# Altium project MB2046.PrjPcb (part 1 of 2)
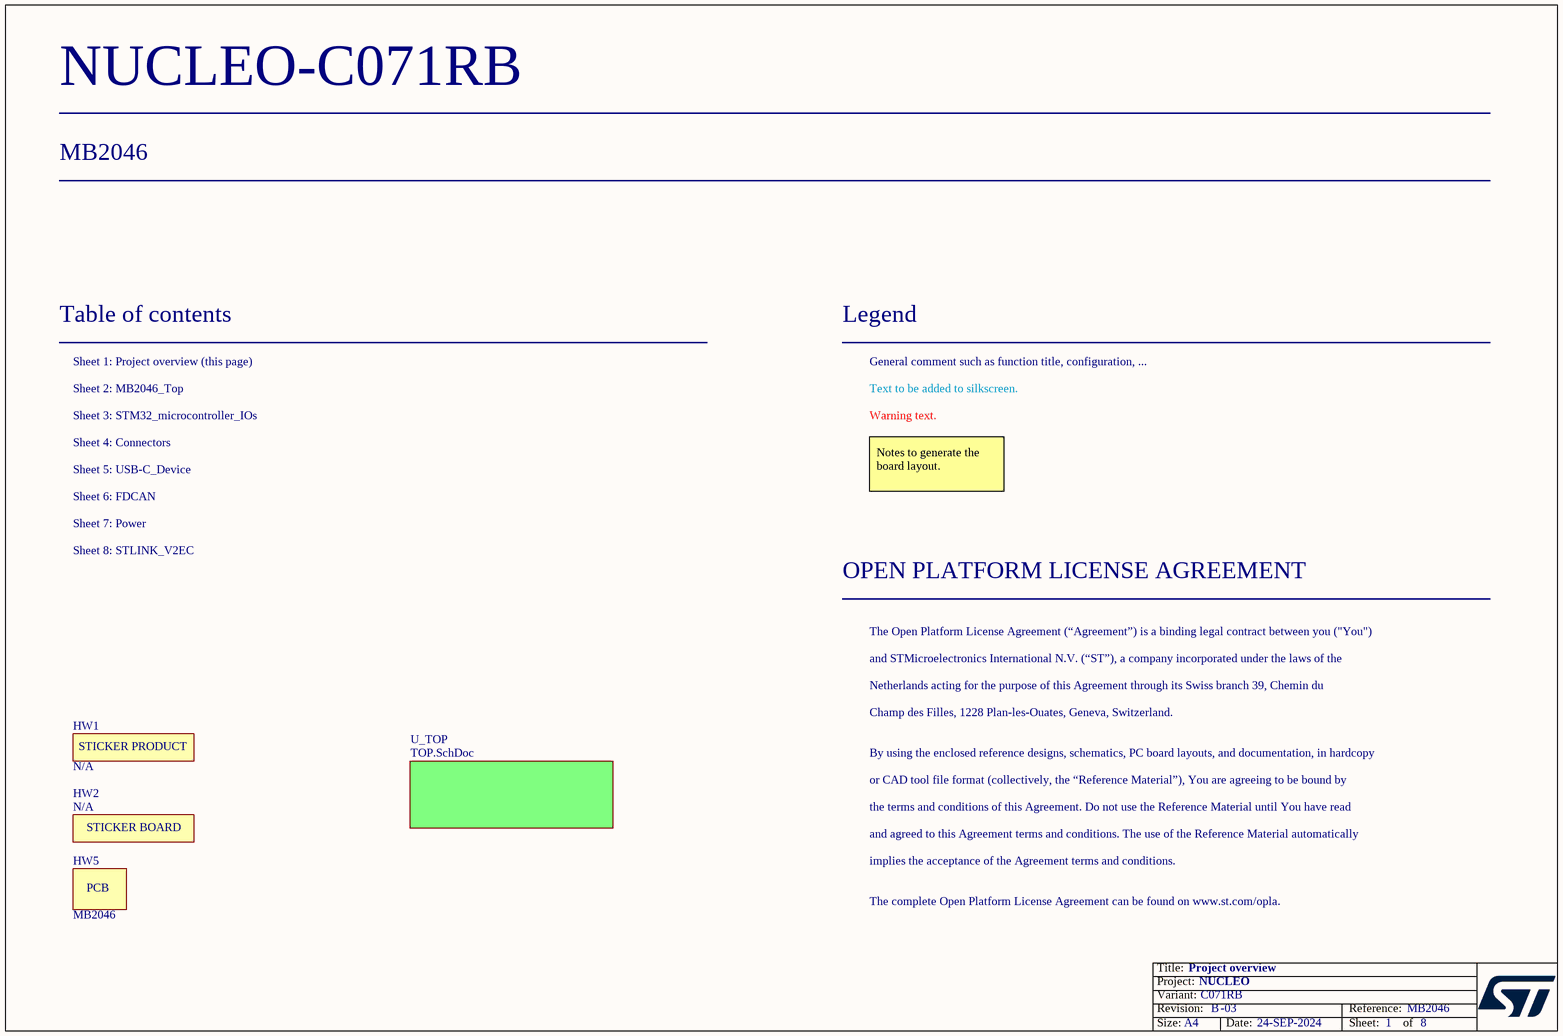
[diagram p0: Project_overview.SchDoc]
VariantName: C071RB; Board_Reference: MB2046; Board_PCB_Revision: B; Board_Name: NUCLEO; Board_Document_Date: 24-SEP-2024; Board_Assembly_Revision: 03
8 sheets, 190 parts. Net scope: flat (ports and power ports of the same name join across sheets).
Board file: MB2046.PcbDoc
Sheets:
  Project_overview.SchDoc
    U_TOP = TOP.SchDoc
      Power = Power.SchDoc
      U_STM32_microcontroller_IOs = STM32_microcontroller_IOs.SchDoc
      U_STLINK_V2EC = STLINK_V2EC.SchDoc
      U_USB-C_Device = USB-C_Device.SchDoc
      U_FDCAN = FDCAN.SchDoc
      U_Connectors = Connectors.SchDoc

## Sheet Project_overview.SchDoc: Project overview
size A4; Date: Not used; ApprovedBy: Not used; CheckedBy: Not used; Author: Not used; CompanyName: STMicroelectronics; DrawnBy: Not used; Engineer: Not used; Organization: Not used; Address1: Not used; Address2: Not used; Address3: Not used; Address4: Not used; DocumentNumber: 1; Revision: Not used; SheetNumber: 1; SheetTotal: 8

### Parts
HW1  STICKER_PRODUCT  [STICKER_PRODUCT_25X9]  (value not drawn)  (no BOM)
HW2  STICKER_BOARD  [STICKER_BOARD_25X9]  (value not drawn)  (no BOM)
HW5  value MB2046  (hidden comment: PCB)  (no BOM)

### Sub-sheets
U_TOP = TOP.SchDoc: no entries

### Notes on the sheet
- Table of contents
- Sheet 1: Project overview (this page)
- Legend
- General comment such as function title, configuration, ...
- Sheet 2: MB2046_Top
- Sheet 4: Connectors
- Sheet 3: STM32_microcontroller_IOs
- Text to be added to silkscreen.
- Warning text.
- Sheet 5: USB-C_Device
- Sheet 6: FDCAN
- Notes to generate the board layout.
- Sheet 7: Power
- Sheet 8: STLINK_V2EC
- OPEN PLATFORM LICENSE AGREEMENT
- The Open Platform License Agreement (“Agreement”) is a binding legal contract between you ("You")
- and STMicroelectronics International N.V. (“ST”), a company incorporated under the laws of the
- Netherlands acting for the purpose of this Agreement through its Swiss branch 39, Chemin du
- Champ des Filles, 1228 Plan-les-Ouates, Geneva, Switzerland.
- By using the enclosed reference designs, schematics, PC board layouts, and documentation, in hardcopy
- or CAD tool file format (collectively, the “Reference Material”), You are agreeing to be bound by
- the terms and conditions of this Agreement. Do not use the Reference Material until You have read
- and agreed to this Agreement terms and conditions. The use of the Reference Material automatically
- implies the acceptance of the Agreement terms and conditions.
- The complete Open Platform License Agreement can be found on www.st.com/opla.

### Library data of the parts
HW1 = MCD-00547: Sticker product, 25x9mm; Part_Type: Misc; Part_Preference: Recommended; ShowFields: YES; ID: 3197; Component_Country_Of_Origin: Unknown
HW2 = MCD-00235: Sticker Board, 25x9mm; Part_Type: Misc; Part_Preference: Recommended; ShowFields: YES; ID: 2632; Component_Country_Of_Origin: Unknown
HW5 = MCD-03651: MB2046 PCB; Part_Preference: Recommended; ShowFields: YES; ID: 5767

## Sheet TOP.SchDoc: TOP
size A4; CompanyName: STMicroelectronics; Organization: Microcontrollers Division; SheetNumber: 2; SheetTotal: 8
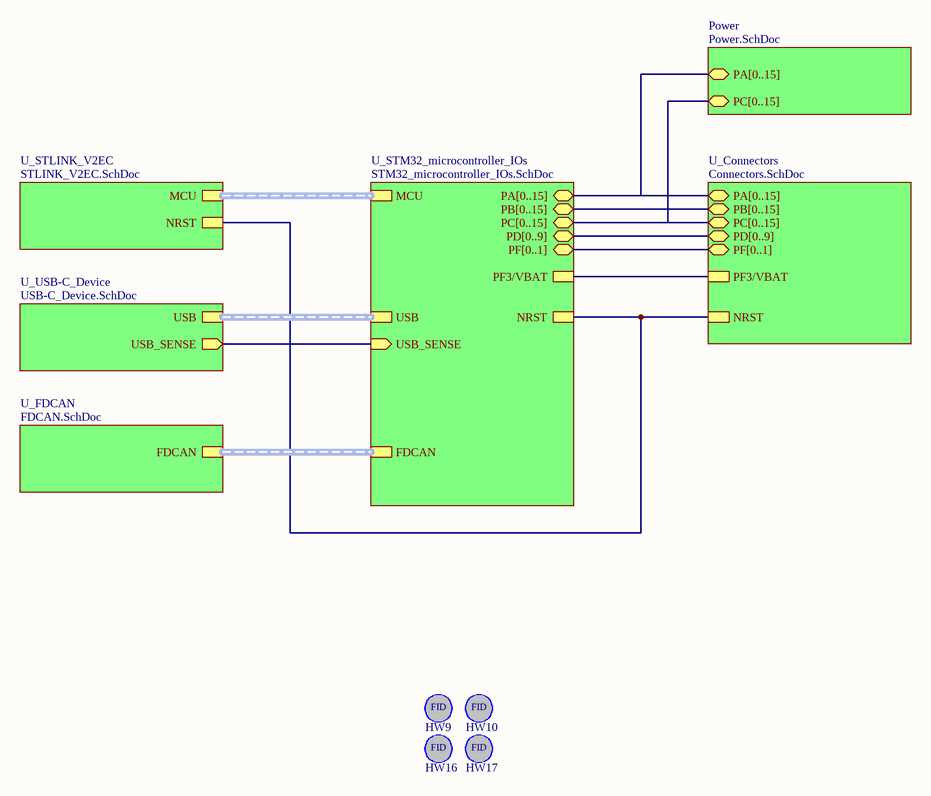
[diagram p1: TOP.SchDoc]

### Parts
HW9  FiducialPad  [MIRE_PLACE_SMD_0P8MM]  (value not drawn)  (no BOM)
HW10  FiducialPad  [MIRE_PLACE_SMD_0P8MM]  (value not drawn)  (no BOM)
HW16  FiducialPad  [MIRE_PLACE_SMD_0P8MM]  (value not drawn)  (no BOM)
HW17  FiducialPad  [MIRE_PLACE_SMD_0P8MM]  (value not drawn)  (no BOM)

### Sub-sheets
Power = Power.SchDoc: PA[0..15] (bidir), PC[0..15] (bidir)
U_Connectors = Connectors.SchDoc: PB[0..15] (bidir), PC[0..15] (bidir), PA[0..15] (bidir), NRST, PD[0..9] (bidir), PF[0..1] (bidir), PF3/VBAT
U_FDCAN = FDCAN.SchDoc: FDCAN (harness FDCAN)
U_STLINK_V2EC = STLINK_V2EC.SchDoc: MCU (harness MCU), NRST
U_STM32_microcontroller_IOs = STM32_microcontroller_IOs.SchDoc: PA[0..15] (bidir), PB[0..15] (bidir), PC[0..15] (bidir), MCU (harness MCU), NRST, USB_SENSE (in), USB (harness USB), PD[0..9] (bidir), PF[0..1] (bidir), PF3/VBAT, FDCAN (harness FDCAN)
U_USB-C_Device = USB-C_Device.SchDoc: USB (harness USB), USB_SENSE (out)

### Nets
(unnamed): sheet U_STM32_microcontroller_IOs/NRST, sheet U_STLINK_V2EC/NRST, sheet U_Connectors/NRST
(unnamed): sheet U_STM32_microcontroller_IOs/USB_SENSE, sheet U_USB-C_Device/USB_SENSE  [a separate net that carries the same name]
(unnamed): sheet U_STM32_microcontroller_IOs/PF3/VBAT, sheet U_Connectors/PF3/VBAT  [a separate net that carries the same name]

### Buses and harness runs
bus sheet Power/PA[0..15] = sheet U_Connectors/PA[0..15] = sheet U_STM32_microcontroller_IOs/PA[0..15]
bus sheet Power/PC[0..15] = sheet U_Connectors/PC[0..15] = sheet U_STM32_microcontroller_IOs/PC[0..15]
bus sheet U_Connectors/PB[0..15] = sheet U_STM32_microcontroller_IOs/PB[0..15]
bus sheet U_Connectors/PD[0..9] = sheet U_STM32_microcontroller_IOs/PD[0..9]
bus sheet U_Connectors/PF[0..1] = sheet U_STM32_microcontroller_IOs/PF[0..1]
harness sheet U_FDCAN/FDCAN = sheet U_STM32_microcontroller_IOs/FDCAN
harness sheet U_STLINK_V2EC/MCU = sheet U_STM32_microcontroller_IOs/MCU
harness sheet U_STM32_microcontroller_IOs/USB = sheet U_USB-C_Device/USB

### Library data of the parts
HW9 HW10 HW16 HW17 = MCD-03135: Fiducial Pad, 0.8mm; Part_Type: Misc; Part_Preference: Recommended; ShowFields: YES; ID: 5251; Component_Country_Of_Origin: Unknown

## Sheet Power.SchDoc: Power
size A4; CompanyName: STMicroelectronics; Organization: Microcontrollers Division; SheetNumber: 7; SheetTotal: 8
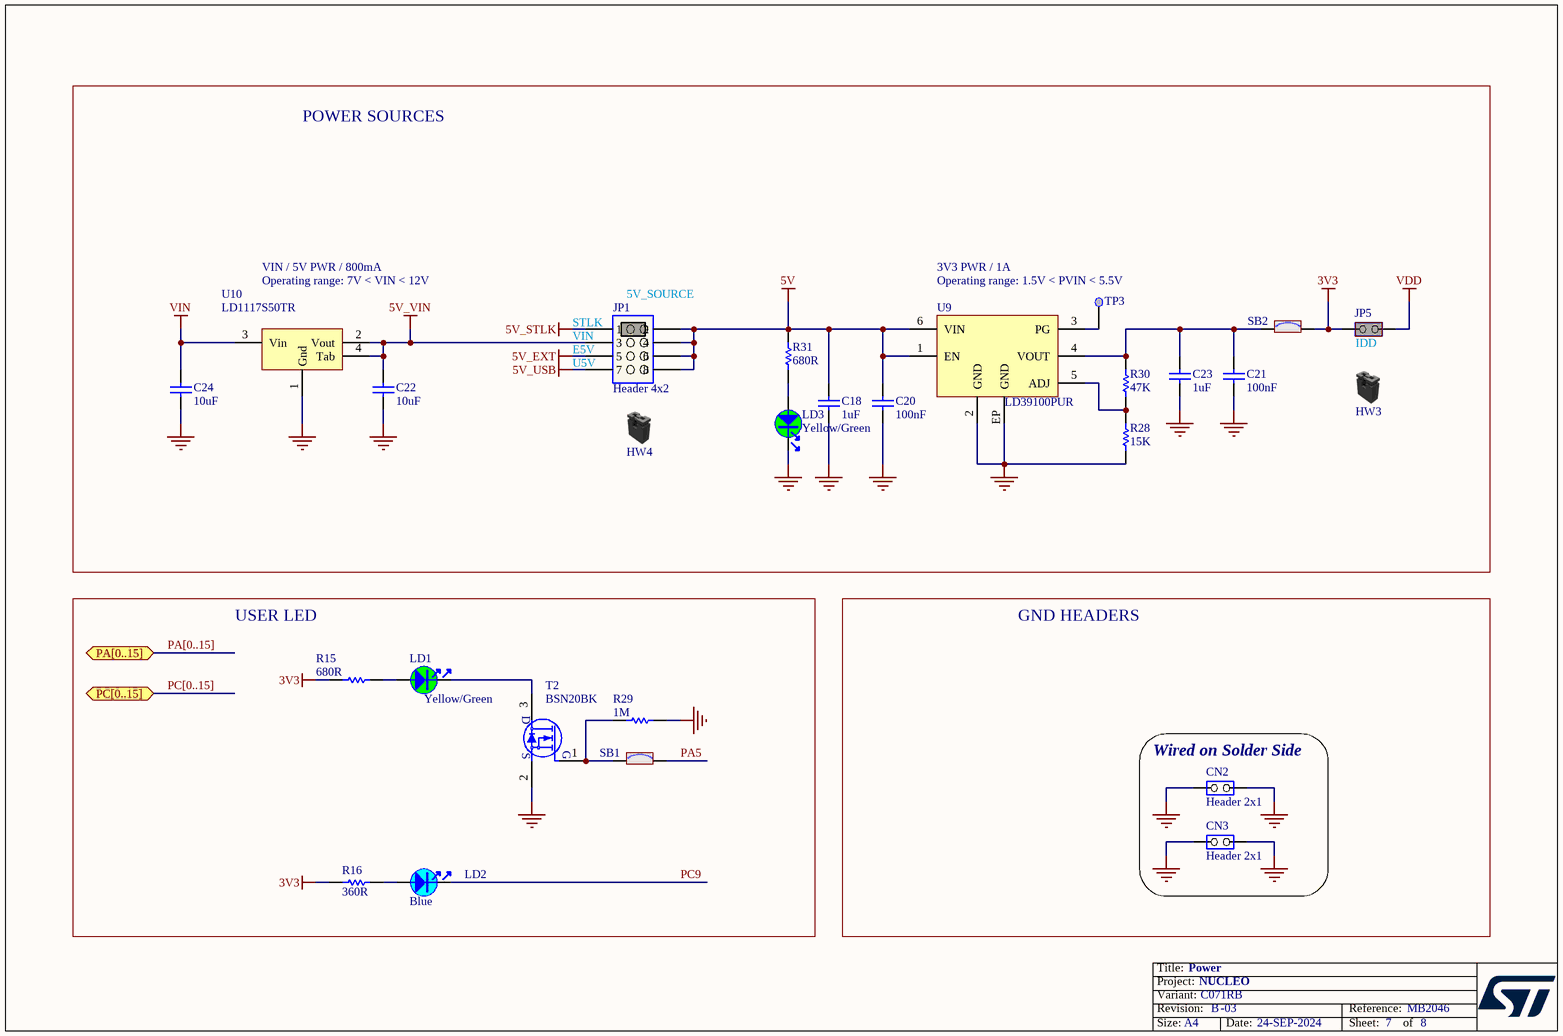
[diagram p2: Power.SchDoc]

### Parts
C18  value 1uF  [C0603]  (hidden comment: Capacitor)
C20  value 100nF  [C0402]  (hidden comment: Capacitor)
C21  value 100nF  [C0402]  (hidden comment: Capacitor)
C22  value 10uF  [C0805]  (hidden comment: Capacitor)
C23  value 1uF  [C0603]  (hidden comment: Capacitor)
C24  value 10uF  [C0805]  (hidden comment: Capacitor)
CN2  value Header 2x1  [CON_SAMTEC_TSW-102-09-X-S]  (hidden comment: Jumper_Header 2x1)
CN3  value Header 2x1  [CON_SAMTEC_TSW-102-09-X-S]  (hidden comment: Jumper_Header 2x1)
HW3  Shunt Black 2.54mm  (value not drawn)  (mechanical)
HW4  Shunt Black 2.54mm  (value not drawn)  (mechanical)
JP1  value Header 4x2  [CON_SAMTEC_TSW-104-07-X-D]  (hidden comment: Jumper_Header 4x2 Fitted 1-2)
JP5  Jumper_Header 2x1 Fitted  [CON_SAMTEC_TSW-102-07-G-S]  (value not drawn)
LD1  value Yellow/Green  [LED_0402_EVERLIGHT_16-213SYGC/S530-E3-TR8 _YELLOW-GREEN_1A2K_H0P45]  (hidden comment: LED_green)
LD2  value Blue  [LED_0402_KINGBRIGHT_KPHHS-1005QBC-D-V_BLUE_1A2K_H0P5]  (hidden comment: LED_blue)
LD3  value Yellow/Green  [LED_0402_EVERLIGHT_16-213SYGC/S530-E3-TR8 _YELLOW-GREEN_1A2K_H0P45]  (hidden comment: LED_green)
R15  value 680R  [R0402]  (hidden comment: Resistor)
R16  value 360R  [R0402]  (hidden comment: Resistor)
R28  value 15K  [R0402]  (hidden comment: Resistor)
R29  value 1M  [R0402]  (hidden comment: Resistor)
R30  value 47K  [R0402]  (hidden comment: Resistor)
R31  value 680R  [R0402]  (hidden comment: Resistor)
SB1  SB_ON  [SOLDER-BRIDGE_R0603-0R]  (value not drawn)
SB2  SB_ON  [SOLDER-BRIDGE_R0603-0R]  (value not drawn)
T2  value BSN20BK  [MOS_SOT23]  (hidden comment: BSN20)
TP3  Test Point  [TP_SMD_1MM]  (value not drawn)  (no BOM)
U9  LD39100PUR  [ICC_DFN6-EPAD_3X3_P095]
U10  LD1117S50TR  [REG_SOT223-TAB]

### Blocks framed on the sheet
POWER SOURCES: C18 C20-C24 HW3 HW4 JP1 JP5 LD3 R28 R30 R31 SB2 TP3 U9 U10
USER LED: LD1 LD2 R15 R16 R29 SB1 T2
Wired on Solder Side: CN2 CN3

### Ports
PA[0..15] (bidir), PC[0..15] (bidir)

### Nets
3V3: JP5.2(NO) R15.2 R16.2 SB2.2
5V: C18.2 C20.2 JP1.2 JP1.4 JP1.6 JP1.8 R31.1 U9.1(EN) U9.6(VIN)
5V_EXT: JP1.5
5V_STLK: JP1.1
5V_USB: JP1.7
5V_VIN: C22.2 JP1.3 U10.2(Vout) U10.4(Tab)
GND: C18.1 C20.1 C21.1 C22.1 C23.1 C24.1 CN2.1(COMMON) CN2.2(NO) CN3.1(COMMON) CN3.2(NO) LD3.2 R28.1 R29.2 T2.2(S) U9.2(GND) U9.EP(GND) U10.1(Gnd)
VDD: JP5.1(COMMON)
VIN: C24.2 U10.3(Vin)
PA5: SB1.2
PC9: LD2.2
NetC21_2: C21.2 C23.2 R30.2 SB2.1 U9.4(VOUT)
NetLD1_1: LD1.1 R15.1
NetLD1_2: LD1.2 T2.3(D)
NetLD2_1: LD2.1 R16.1
NetLD3_1: LD3.1 R31.2
NetR28_2: R28.2 R30.1 U9.5(ADJ)
NetR29_1: R29.1 SB1.1 T2.1(G)
NetTP3_1: TP3.1 U9.3(PG)

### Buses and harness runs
bus PA[0..15] = port PA[0..15]
bus PC[0..15] = port PC[0..15]

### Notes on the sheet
- VIN / 5V PWR / 800mA
- Operating range: 7V < VIN < 12V
- (near JP1) 5V_SOURCE
- 3V3 PWR / 1A
- (near TP3) Operating range: 1.5V < PVIN < 5.5V
- (near JP1) E5V
- (near JP1) VIN
- (near JP1) STLK
- (near JP1) U5V
- (near JP5) IDD
- GND HEADERS

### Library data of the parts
C18 C23 = MCD-00010: Capacitor, MLCC, 1uF, 16V, X5R, +/-10%, 0603, T=0.8mm; Manufacturer_Part_Number: CC0603KRX5R7BB105; Manufacturer: YAGEO; Part_Preference: Recommended; Order_Code_RS: 2370680; Component_Country_Of_Origin: China; ShowFields: YES; ID: 2470
C20 C21 = MCD-00006: Capacitor, MLCC, 100nF, 16V, X7R, +/-10%, 0402, T=0.5mm; Manufacturer_Part_Number: CC0402KRX7R7BB104; Manufacturer: YAGEO; Part_Preference: Recommended; Partial_Alternate_Internal_Part_Number: MCD-03299; Order_Code_RS: 9402047; Component_Country_Of_Origin: China; ShowFields: YES; ID: 2474
C22 C24 = MCD-00014: Capacitor, MLCC, 10uF, 25V, X5R, +/-10%, 0805, T=0.85mm; Manufacturer_Part_Number: CC0805KRX5R8BB106; Manufacturer: YAGEO; Part_Preference: Recommended; Full_Alternate_Internal_Part_Number: MCD-02385; Partial_Alternate_Internal_Part_Number: MCD-03053; Component_Country_Of_Origin: China; ShowFields: YES; ID: 2468
CN2 CN3 = MCD-00214: Header, 2x1, 2.54mm, VR, TH, T=5.84mm/10.16mm; Part_Type: Connector; Manufacturer_Part_Number: TSW-102-09-G-S; Manufacturer: SAMTEC; Part_Preference: Recommended; Full_Alternate_Internal_Part_Number: MCD-02393; Partial_Alternate_Internal_Part_Number: MCD-03591, MCD-03719, MCD-04227; Order_Code_RS: 180-3129; Component_Country_Of_Origin: China, Costa Rica, Malaysia, USA, Vietnam; ShowFields: YES; ID: 2652
HW3 HW4 = MCD-00043: Jumper, 2.54mm, Black, 4.3A, 6.1mm, 5mR; Manufacturer_Part_Number: SNT-100-BK-G; Manufacturer: SAMTEC; Part_Type: Misc; Part_Preference: Recommended; Full_Alternate_Internal_Part_Number: MCD-02388; Partial_Alternate_Internal_Part_Number: MCD-01849, MCD-01864; Manufacturer_HQ_COO: Unknown; Value: SNT-100-BK-G; Component_Country_Of_Origin: China, Costa Rica, Malaysia, USA, Vietnam; ShowFields: YES; ID: 2551; Order_Code_RS: 158-7784; Alternate_EMS: A
JP1 = MCD-00686: Header, 4x2, 2.54mm, VR, TH, T=5.84mm/2.54mm; Part_Type: Connector; Manufacturer_Part_Number: TSW-104-07-G-D; Manufacturer: SAMTEC; Part_Preference: Recommended; Partial_Alternate_Internal_Part_Number: MCD-01661, MCD-03721; Order_Code_RS: 161-2260; Component_Country_Of_Origin: China, Costa Rica, Malaysia, USA, Vietnam; ShowFields: YES; ID: 3062
JP5 = MCD-00683: Header, 2x1, 2.54mm, VR, TH, T=5.84mm/2.54mm; Part_Type: Connector; Manufacturer_Part_Number: TSW-102-07-G-S; Manufacturer: SAMTEC; Part_Preference: Recommended; Full_Alternate_Internal_Part_Number: MCD-02389; Partial_Alternate_Internal_Part_Number: MCD-02957, MCD-03720; Order_Code_RS: 155-5312; Component_Country_Of_Origin: China, Costa Rica, Malaysia, USA, Vietnam; ShowFields: YES; ID: 3057
LD1 LD3 = MCD-02330: LED Bicolor, Yellow/Green, 2V, 25mA, 0402; Part_Type: Display; Manufacturer_Part_Number: 16-213SYGC/S530-E3/TR8; Manufacturer: EVERLIGHT; Part_Preference: Recommended; Component_Country_Of_Origin: China; ShowFields: YES; ID: 4436
LD2 = MCD-00706: LED, Blue, 3V3, 20mA, 0402; Part_Type: Display; Part_Preference: Recommended; Manufacturer: KINGBRIGHT; Manufacturer_Part_Number: KPHHS-1005QBC-D-V; Order_Code_RS: 146-1490; Component_Country_Of_Origin: Unknown; ShowFields: YES; ID: 3040
R15 R31 = MCD-00507: Resistor, 680R, 0402, +/-1%, 1/16W; Manufacturer_Part_Number: RC0402FR-07680RL; Manufacturer: YAGEO; Part_Preference: Recommended; Component_Country_Of_Origin: China; ShowFields: YES; ID: 3238
R16 = MCD-00461: Resistor, 360R, 0402, +/-1%, 1/16W; Manufacturer_Part_Number: RC0402FR-07360RL; Manufacturer: YAGEO; Part_Preference: Recommended; Component_Country_Of_Origin: China; ShowFields: YES; ID: 2816
R28 = MCD-01943: Resistor, 15K, 0402, +/-1%, 1/16W; Part_Preference: Recommended; Manufacturer: YAGEO; Manufacturer_Part_Number: RC0402FR-0715KL; Order_Code_RS: 618-6009; Component_Country_Of_Origin: China; ShowFields: YES; ID: 4043
R29 = MCD-00182: Resistor, 1M, 0402, +/-1%, 1/16W; Manufacturer_Part_Number: RC0402FR-071ML; Manufacturer: YAGEO; Part_Preference: Recommended; BMS_Part_Number: 9131778; Order_Code_RS: 618-6194; Component_Country_Of_Origin: China; ShowFields: YES; ID: 2686
R30 = MCD-00063: Resistor, 47K, 0402, +/-1%, 1/16W; Part_Preference: Recommended; Manufacturer: YAGEO; Manufacturer_Part_Number: RC0402FR-0747KL; Order_Code_RS: 9239430; Component_Country_Of_Origin: China; ShowFields: YES; ID: 2528
SB1 SB2 = MCD-00071: Resistor, 0R, SB0603, 5%, 0.1W; Manufacturer_Part_Number: RC0603JR-070RL; Manufacturer: YAGEO; Part_Preference: Recommended; Manufacturer_HQ_COO: Unknown; ShowFields: YES; ID: 2521; Order_Code_RS: 199-5647; Component_Country_Of_Origin: China
T2 = MCD-01969: Transistor, MOSFET, N-CH, 60V, 265mA, SOT23-3; Manufacturer: NEXPERIA; Part_Preference: Recommended; Order_Code_RS: 136-4845; Component_Country_Of_Origin: China; ShowFields: YES; ID: 4069
TP3 = MCD-00074: Test Point, SMD, 1mm; Part_Type: Misc; Part_Preference: Recommended; ShowFields: YES; ID: 2518; Component_Country_Of_Origin: Unknown
U9 = MCD-03339: LDO, 1V5 to 5V5V, 1A adjustable; Part_Type: IC; Part_Preference: Recommended; Manufacturer: STMICROELECTRONICS; ShowFields: YES; ID: 5455; Component_Country_Of_Origin: Malaysia
U10 = MCD-00088: LDO, Adjustable and fixed low drop positive voltage regulator; Part_Type: IC; Manufacturer: STMICROELECTRONICS; BMS_Part_Number: 9176133; Part_Preference: Recommended; Manufacturer_HQ_COO: EU; Component_Country_Of_Origin: China; ShowFields: YES; ID: 2503; Order_Code_RS: 165-7748

## Sheet STM32_microcontroller_IOs.SchDoc: STM32_microcontroller_IOs
size A4; CompanyName: STMicroelectronics; Organization: Microcontrollers Division; SheetNumber: 3; SheetTotal: 8
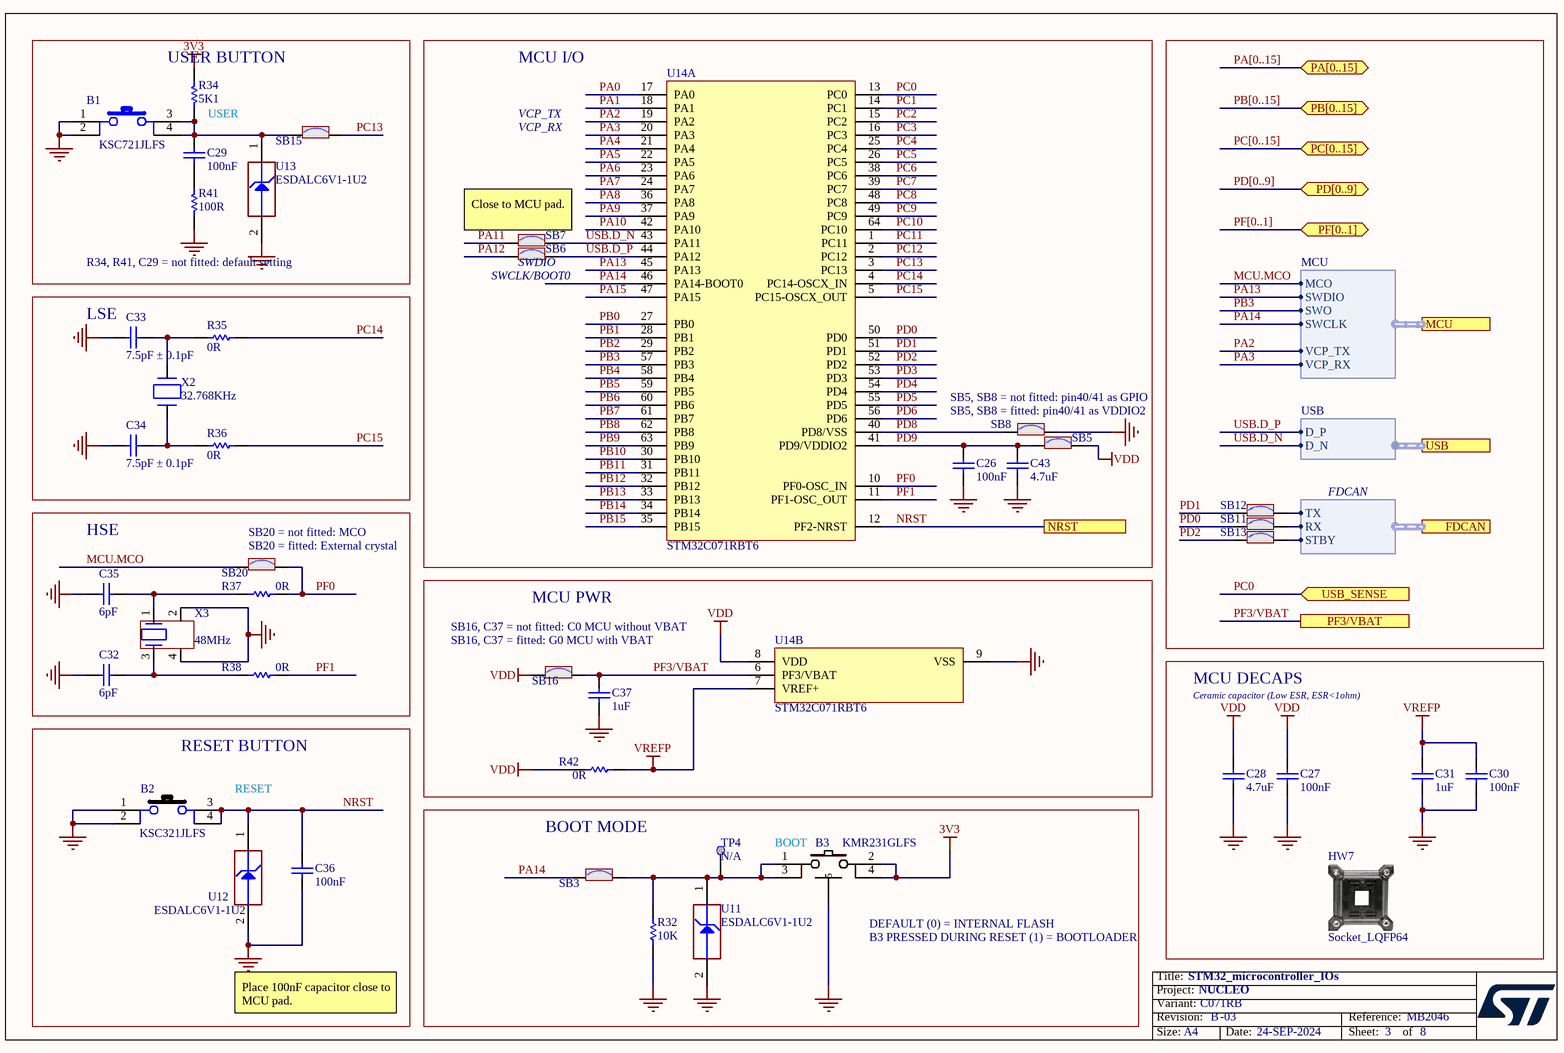
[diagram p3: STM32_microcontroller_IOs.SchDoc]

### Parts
B1  value KSC721JLFS  [SWI_C&K_KSC721JLFS_BLUE]  (hidden comment: SW_BLUE_KSC721JLFS)
B2  value KSC321JLFS  [SWI_C&K_KSC321JLFS_BLACK]  (hidden comment: SW_BLACK_KSC321JLFS)
B3  value KMR231GLFS  [SWI_C&K_Y78B23110FP__ITT_KMR231GLFS]  (hidden comment: SW-PUSH-CMS_KMR2_BLACK)
C26  value 100nF  [C0402]  (hidden comment: Capacitor)
C27  value 100nF  [C0402]  (hidden comment: Capacitor)
C28  value 4.7uF  [C0603_H0P8]  (hidden comment: Capacitor)
C29  value 100nF  [C0402]  (hidden comment: Capacitor)
C30  value 100nF  [C0402]  (hidden comment: Capacitor)
C31  value 1uF  [C0603]  (hidden comment: Capacitor)
C32  value 6pF  [C0402]  (hidden comment: Capacitor)
C33  value 7.5pF ± 0.1pF  [C0402]  (hidden comment: Capacitor)
C34  value 7.5pF ± 0.1pF  [C0402]  (hidden comment: Capacitor)
C35  value 6pF  [C0402]  (hidden comment: Capacitor)
C36  value 100nF  [C0402]  (hidden comment: Capacitor)
C37  value 1uF  [C0603]  (hidden comment: Capacitor)
C43  value 4.7uF  [C0603_H0P8]  (hidden comment: Capacitor)
HW7  SOCKET_LQFP64  (mechanical)
R32  value 10K  [R0402]  (hidden comment: Resistor)
R34  value 5K1  [R0402]  (hidden comment: Resistor)
R35  value 0R  [R0402]  (hidden comment: Resistor)
R36  value 0R  [R0402]  (hidden comment: Resistor)
R37  value 0R  [R0402]  (hidden comment: Resistor)
R38  value 0R  [R0402]  (hidden comment: Resistor)
R41  value 100R  [R0402]  (hidden comment: Resistor)
R42  value 0R  [R0603]  (hidden comment: Resistor)
SB3  SB_ON  [SOLDER-BRIDGE_R0603-0R]  (value not drawn)
SB5  SB_ON  [SOLDER-BRIDGE_R0603-0R]  (value not drawn)
SB6  SB_ON  [SOLDER-BRIDGE_R0603-0R]  (value not drawn)
SB7  SB_ON  [SOLDER-BRIDGE_R0603-0R]  (value not drawn)
SB8  SB_ON  [SOLDER-BRIDGE_R0603-0R]  (value not drawn)
SB11  SB_ON  [SOLDER-BRIDGE_R0603-0R]  (value not drawn)
SB12  SB_ON  [SOLDER-BRIDGE_R0603-0R]  (value not drawn)
SB13  SB_ON  [SOLDER-BRIDGE_R0603-0R]  (value not drawn)
SB15  SB_ON  [SOLDER-BRIDGE_R0603-0R]  (value not drawn)
SB16  SB_ON  [SOLDER-BRIDGE_R0603-0R]  (value not drawn)
SB20  SB_ON  [SOLDER-BRIDGE_R0603-0R]  (value not drawn)
TP4  Test Point  [TP_SMD_0-6MM]  (value not drawn)  (no BOM)
U11  value ESDALC6V1-1U2  [ESD_ST0201]  (hidden comment: ESD-TRANSIL)
U12  value ESDALC6V1-1U2  [ESD_ST0201]  (hidden comment: ESD-TRANSIL)
U13  value ESDALC6V1-1U2  [ESD_ST0201]  (hidden comment: ESD-TRANSIL)
U14  value STM32C071RBT6  [ICC_LQFP64_10X10_P050_SOCKET_YAMAICHI_IC149-064-069-B5_NM]  (hidden comment: STM32C071RB)  (parts A,B of 2)
X2  value 32.768KHz  [CRY_NX2012SA_2P]  (hidden comment: XTAL_2_PINS)
X3  value 48MHz  [CRY_NX1612SA_4P]  (hidden comment: XTAL_4_PINS)

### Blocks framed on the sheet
USER BUTTON: B1 C29 R34 R41 SB15 U13
MCU I/O: C26 C43 SB5-SB8 U14
LSE: C33 C34 R35 R36 X2
HSE: C32 C35 R37 R38 SB20 X3
MCU PWR: C37 R42 SB16 U14
MCU DECAPS: C27 C28 C30 C31 HW7
RESET BUTTON: B2 C36 U12
BOOT MODE: B3 R32 SB3 TP4 U11

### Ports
FDCAN (harness FDCAN), MCU (harness MCU), NRST, PA[0..15] (bidir), PB[0..15] (bidir), PC[0..15] (bidir), PD[0..9] (bidir), PF3/VBAT, PF[0..1] (bidir), USB (harness USB), USB_SENSE (in)

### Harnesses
MCU: MCO, SWDIO, SWO, VCP_TX, SWCLK, VCP_RX
USB: D_P, D_N
FDCAN: TX, RX, STBY

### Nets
3V3: B3.2 B3.4 R34.2
GND: B1.1 B1.2 B2.1 B2.2 B3.5 C26.1 C27.1 C28.1 C30.1 C31.2 C32.1 C33.1 C34.1 C35.1 C36.1 C37.2 C43.1 R32.1 R41.2 SB8.2 U11.2(GND) U12.2(GND) U13.2(GND) U14.9(VSS) X3.2 X3.4
VDD: C27.2 C28.2 R42.1 SB5.2 SB16.1 U14.8(VDD)
VREFP: C30.2 C31.1 R42.2 U14.7(VREF+)
FDCAN_RX: SB11.2 ; port FDCAN.RX
FDCAN_STBY: SB13.2 ; port FDCAN.STBY
FDCAN_TX: SB12.2 ; port FDCAN.TX
MCU.MCO: SB20.1 ; port MCU.MCO
NRST: B2.3 B2.4 C36.2 U12.1(IO1) U14.12(PF2-NRST) ; port NRST
PA0: U14.17(PA0)
PA1: U14.18(PA1)
PA2: U14.19(PA2) ; port MCU.VCP_TX  [project net MCU.VCP_TX]
PA3: U14.20(PA3) ; port MCU.VCP_RX  [project net MCU.VCP_RX]
PA4: U14.21(PA4)
PA5: U14.22(PA5)
PA6: U14.23(PA6)
PA7: U14.24(PA7)
PA8: U14.36(PA8)
PA9: U14.37(PA9)
PA10: U14.42(PA10)
PA11: SB7.1
PA12: SB6.1
PA13: U14.45(PA13) ; port MCU.SWDIO  [project net MCU.SWDIO]
PA14: SB3.1 U14.46(PA14-BOOT0) ; port MCU.SWCLK  [project net MCU.SWCLK]
PA15: U14.47(PA15)
PB0: U14.27(PB0)
PB1: U14.28(PB1)
PB2: U14.29(PB2)
PB3: U14.57(PB3) ; port MCU.SWO  [project net MCU.SWO]
PB4: U14.58(PB4)
PB5: U14.59(PB5)
PB6: U14.60(PB6)
PB7: U14.61(PB7)
PB8: U14.62(PB8)
PB9: U14.63(PB9)
PB10: U14.30(PB10)
PB11: U14.31(PB11)
PB12: U14.32(PB12)
PB13: U14.33(PB13)
PB14: U14.34(PB14)
PB15: U14.35(PB15)
PC0: U14.13(PC0) ; port USB_SENSE
PC1: U14.14(PC1)
PC2: U14.15(PC2)
PC3: U14.16(PC3)
PC4: U14.25(PC4)
PC5: U14.26(PC5)
PC6: U14.38(PC6)
PC7: U14.39(PC7)
PC8: U14.48(PC8)
PC9: U14.49(PC9)
PC10: U14.64(PC10)
PC11: U14.1(PC11)
PC12: U14.2(PC12)
PC13: SB15.2 U14.3(PC13)
PC14: R35.2 U14.4(PC14-OSCX_IN)
PC15: R36.2 U14.5(PC15-OSCX_OUT)
PD0: SB11.1 U14.50(PD0)
PD1: SB12.1 U14.51(PD1)
PD2: SB13.1 U14.52(PD2)
PD3: U14.53(PD3)
PD4: U14.54(PD4)
PD5: U14.55(PD5)
PD6: U14.56(PD6)
PD8: SB8.1 U14.40(PD8/VSS)
PD9: C26.2 C43.2 SB5.1 U14.41(PD9/VDDIO2)
PF0: R37.2 SB20.2 U14.10(PF0-OSC_IN)
PF1: R38.2 U14.11(PF1-OSC_OUT)
PF3/VBAT: C37.1 SB16.2 U14.6(PF3/VBAT) ; port PF3/VBAT
USB.D_N: SB7.2 U14.43(PA11) ; port USB.D_N
USB.D_P: SB6.2 U14.44(PA12) ; port USB.D_P
NetB1_3: B1.3 B1.4 C29.2 R34.1 SB15.1 U13.1(IO1)
NetB3_1: B3.1 B3.3 R32.2 SB3.2 TP4.1 U11.1(IO1)
NetC29_1: C29.1 R41.1
NetC32_2: C32.2 R38.1 X3.3
NetC33_2: C33.2 R35.1 X2.2(X2)
NetC34_2: C34.2 R36.1 X2.1(X1)
NetC35_2: C35.2 R37.1 X3.1

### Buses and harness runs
bus PA[0..15] = port PA[0..15]
bus PB[0..15] = port PB[0..15]
bus PC[0..15] = port PC[0..15]
bus PD[0..9] = port PD[0..9]
bus PF[0..1] = port PF[0..1]

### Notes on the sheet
- (near R34) USER
- VCP_TX
- VCP_RX
- (near SB7) Close to MCU pad.
- R34, R41, C29 = not fitted: default setting
- (near SB6) SWCLK/BOOT0
- (near SB6) SWDIO
- SB5, SB8 = not fitted: pin40/41 as GPIO
- (near SB8) SB5, SB8 = fitted: pin40/41 as VDDIO2
- (near SB20) SB20 = not fitted: MCO
- (near SB20) SB20 = fitted: External crystal
- SB16, C37 = not fitted: C0 MCU without VBAT
- SB16, C37 = fitted: G0 MCU with VBAT
- Ceramic capacitor (Low ESR, ESR<1ohm)
- RESET
- (near B3) BOOT
- (near B3) DEFAULT (0) = INTERNAL FLASH
- B3 PRESSED DURING RESET (1) = BOOTLOADER
- Place 100nF capacitor close to MCU pad.

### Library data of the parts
B1 = MCD-01800: Switch tactile, SPST-NO, 32V, 50mA, 6.2x6.2mm; Part_Type: Misc; Part_Preference: Recommended; Manufacturer: C&K; Manufacturer_HQ_COO: Unknown; Partial_Alternate_Internal_Part_Number: MCD-03151; Component_Country_Of_Origin: France; ShowFields: YES; ID: 3900
B2 = MCD-01799: Switch tactile, SPST-NO, 32V, 50mA, 6.2x6.2mm; Part_Type: Misc; Part_Preference: Recommended; Manufacturer: C&K; Manufacturer_HQ_COO: Unknown; Component_Country_Of_Origin: France; ShowFields: YES; ID: 3899; Order_Code_RS: 894-9091
B3 = MCD-01485: Switch tactile, SPST-NO, 32V, 50mA, 2.8x4.6mm; Part_Type: Misc; Part_Preference: Recommended; Manufacturer: C&K; Manufacturer_HQ_COO: Unknown; Order_Code_RS: 505-9192; Component_Country_Of_Origin: France; ShowFields: YES; ID: 3585
C26 C27 C29 C30 = MCD-00006: as C20 on sheet Power
C28 C43 = MCD-01721: Capacitor, MLCC, 4.7uF, 10V, X5R, +/-10%, 0603, T=0.8mm; Part_Preference: Recommended; Manufacturer: YAGEO; Manufacturer_Part_Number: CC0603KRX5R6BB475; Partial_Alternate_Internal_Part_Number: MCD-03342; Component_Country_Of_Origin: China; ShowFields: YES; ID: 3821; Alternate_EMS: C
C31 C37 = MCD-00010: as C18 on sheet Power
C32 C35 = MCD-03185: Capacitor, MLCC, 6pF, 50V, NPO, +/-0,25pF, 0402, T=0.5mm; Manufacturer_Part_Number: GJM1555C1H6R0CB01; Manufacturer: MURATA; Part_Preference: Recommended; Order_Code_RS: 170-6040; Component_Country_Of_Origin: Singapore; ShowFields: YES; ID: 5301
C33 C34 = MCD-04081: Capacitor, MLCC, 7.5pF, 50V, NP0/C0G, +/-0.1pF, 0402, T=0.5mm; Part_Preference: Recommended; Manufacturer: MURATA; Manufacturer_Part_Number: GJM1555C1H7R5BB01D; Component_Country_Of_Origin: Japan, Singapore; ShowFields: YES; ID: 6197
C36 = MCD-00006: Capacitor, MLCC, 100nF, 16V, X7R, +/-10%, 0402, T=0.5mm; Part_Preference: Recommended; Manufacturer: YAGEO; Manufacturer_Part_Number: CC0402KRX7R7BB104; Partial_Alternate_Internal_Part_Number: MCD-03299; Order_Code_RS: 9402047; Component_Country_Of_Origin: China; ShowFields: YES; ID: 2474
HW7 = MCD-01253: Socket_IC, LQFP64, pitch 0.5mm, with positioning pins; Manufacturer_Part_Number: IC149-064-169-B5; Manufacturer: YAMAICHI; Part_Preference: Forbidden; Component_Country_Of_Origin: Unknown; ShowFields: YES; ID: 3244
R32 = MCD-00053: Resistor, 10K, 0402, +/-1%, 1/16W; BMS_Part_Number: 9131590; Part_Preference: Recommended; Manufacturer: YAGEO; Manufacturer_Part_Number: RC0402FR-0710KL; Order_Code_RS: 9239359; Component_Country_Of_Origin: China; ShowFields: YES; ID: 2539
R34 = MCD-00333: Resistor, 5K1, 0402, +/-1%, 1/16W; Manufacturer_Part_Number: RC0402FR-075K1L; Manufacturer: YAGEO; Part_Preference: Recommended; Component_Country_Of_Origin: China; ShowFields: YES; ID: 2944
R35-R38 = MCD-00052: Resistor, 0R, 0402, +/-5%, 1/16W; Manufacturer_Part_Number: RC0402JR-070RL; Manufacturer: YAGEO; Part_Preference: Recommended; Order_Code_RS: 9232516RL; Component_Country_Of_Origin: China; ShowFields: YES; ID: 2540
R41 = MCD-00067: Resistor, 100R, 0402, +/- 1%, 1/16W; Manufacturer_Part_Number: RC0402FR-07100RL; Manufacturer: YAGEO; Part_Preference: Recommended; Order_Code_RS: 9239111; Component_Country_Of_Origin: China; ShowFields: YES; ID: 2527
R42 = MCD-00056: Resistor, 0R, 0603, +/-5%, 1/10W; Manufacturer_Part_Number: RC0603JR-070RL; Manufacturer: YAGEO; Part_Preference: Recommended; ShowFields: YES; ID: 2536; Order_Code_RS: 9233130RL; Component_Country_Of_Origin: China
SB3 SB5 SB8 SB11-SB13 SB15 SB16 SB20 = MCD-00071: as SB1 on sheet Power
SB6 SB7 = MCD-00071: Resistor, 0R, SB0603, 5%, 0.1W; Manufacturer_Part_Number: RC0603JR-070RL; Manufacturer: YAGEO; Part_Preference: Recommended; Manufacturer_HQ_COO: Unknown; Component_Country_Of_Origin: China; ShowFields: YES; ID: 2521; Order_Code_RS: 199-5647
TP4 = MCD-00631: Test Point, SMD, 0.6mm; Part_Type: Misc; Part_Preference: Recommended; ShowFields: YES; ID: 3108; Component_Country_Of_Origin: Unknown
U11 = MCD-00170: Diode, ESD TVS, 3V, 100nA, 8V, ST0201; Manufacturer: STMICROELECTRONICS; BMS_Part_Number: 9151132; Part_Preference: Recommended; Manufacturer_HQ_COO: EU; Order_Code_RS: 795-8404; Component_Country_Of_Origin: China; ShowFields: YES; ID: 2696
U12 U13 = MCD-00170: Diode, ESD TVS, 3V, 100nA, 8V, ST0201; Manufacturer: STMICROELECTRONICS; BMS_Part_Number: 9151132; Part_Preference: Recommended; Manufacturer_HQ_COO: EU; Component_Country_Of_Origin: China; ShowFields: YES; ID: 2696; Order_Code_RS: 795-8404
U14 = MCD-03542: MCU, ARM Cortex-M0+ 32-bit, 128KB Flash, 18KB RAM; Part_Type: IC; Part_Preference: Recommended; Manufacturer: STMICROELECTRONICS; Component_Country_Of_Origin: Unknown; ShowFields: YES; ID: 5658
X2 = MCD-01479: Crystal, 32.768kHz, 6pF, +/-20ppm, 80K, 2.05x1.2mm; Part_Type: Crystal_Osc; Manufacturer_Part_Number: NX2012SA-32.768KHZ-EXS00A-MU00527; Manufacturer: NDK; BMS_Part_Number: 9157049; Part_Preference: Recommended; Component_Country_Of_Origin: Unknown; ShowFields: YES; ID: 3579
X3 = MCD-02262: Crystal, 48MHz, 7pF, +/-20 ppm, 80R, 1.6x1.2mm; Part_Type: Crystal_Osc; Part_Preference: Recommended; Manufacturer: NDK; Manufacturer_Part_Number: NX1612SA-48MHZ-EXS00A-CS13734; Component_Country_Of_Origin: Unknown; ShowFields: YES; ID: 4362

## Sheet STLINK_V2EC.SchDoc: STLINK-V2EC
size A3; Date: Not used; ApprovedBy: Not used; CheckedBy: Not used; Author: Not used; CompanyName: STMicroelectronics; DrawnBy: Not used; Engineer: Not used; Organization: Not used; Address1: Not used; Address2: Not used; Address3: Not used; Address4: Not used; DocumentNumber: Not used; Revision: V0.1; SheetNumber: 8; SheetTotal: 8
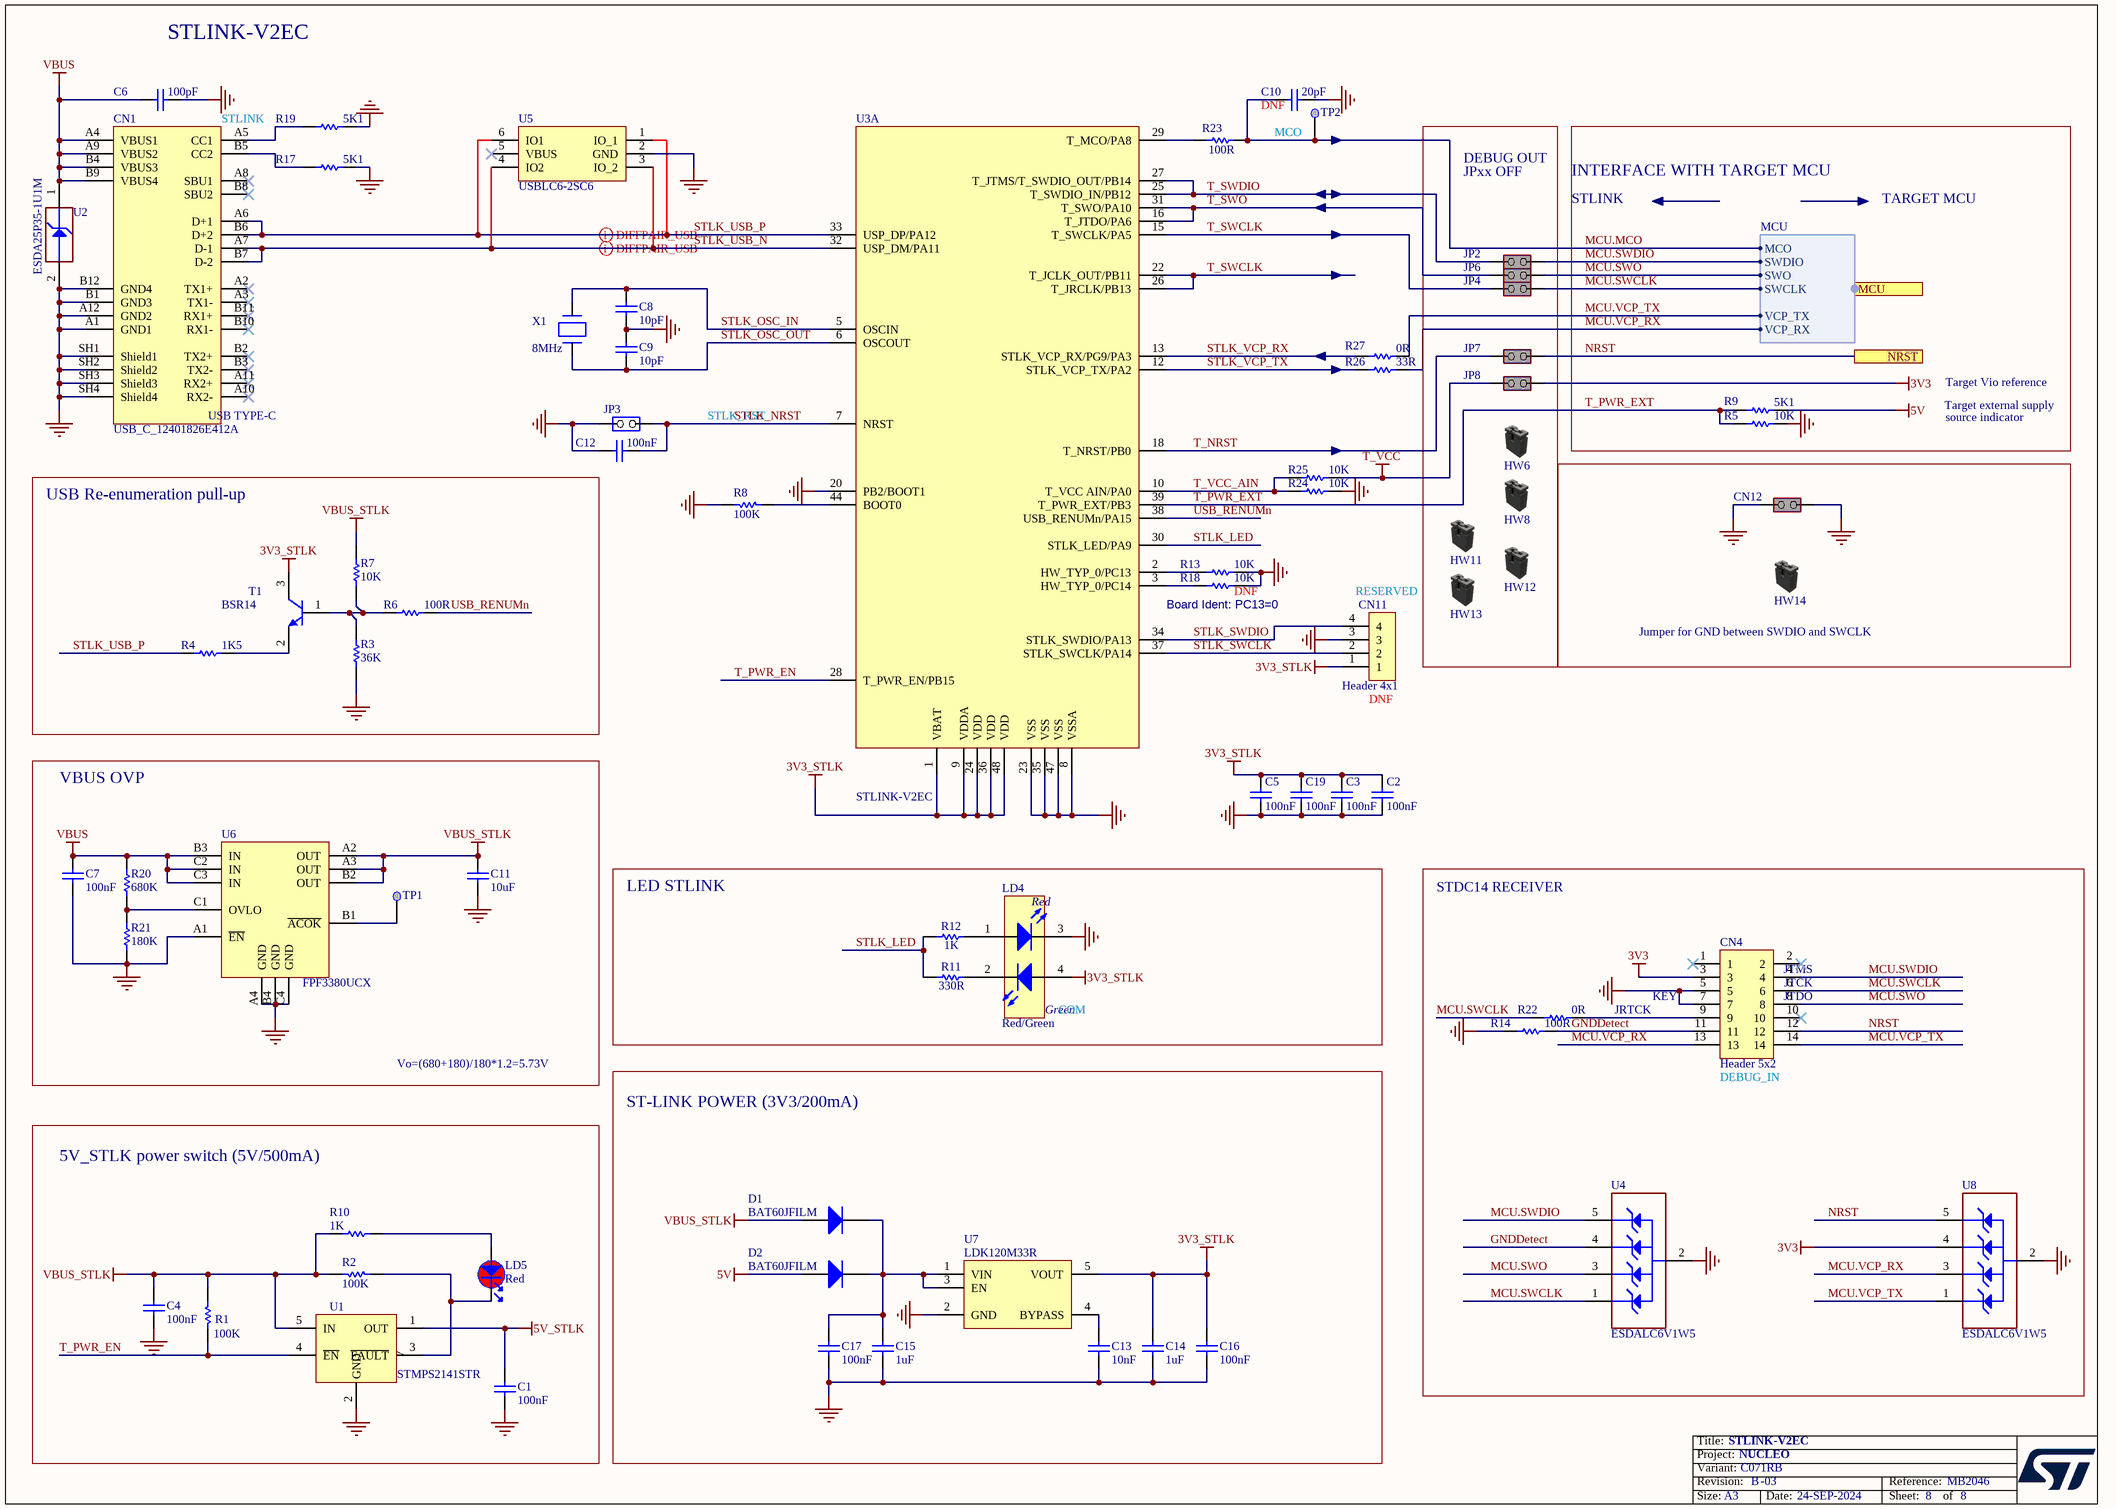
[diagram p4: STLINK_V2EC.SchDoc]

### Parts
C1  value 100nF  [C0402]  (hidden comment: Capacitor)
C2  value 100nF  [C0402]  (hidden comment: Capacitor)
C3  value 100nF  [C0402]  (hidden comment: Capacitor)
C4  value 100nF  [C0402]  (hidden comment: Capacitor)
C5  value 100nF  [C0402]  (hidden comment: Capacitor)
C6  value 100pF  [C0402]  (hidden comment: Capacitor)
C7  value 100nF  [C0603]  (hidden comment: Capacitor)
C8  value 10pF  [C0402]  (hidden comment: Capacitor)
C9  value 10pF  [C0402]  (hidden comment: Capacitor)
C10  value 20pF  [C0402]  (hidden comment: Capacitor)
C11  value 10uF  [C0603]  (hidden comment: Capacitor)
C12  value 100nF  [C0402]  (hidden comment: Capacitor)
C13  value 10nF  [C0402]  (hidden comment: Capacitor)
C14  value 1uF  [C0603]  (hidden comment: Capacitor)
C15  value 1uF  [C0603]  (hidden comment: Capacitor)
C16  value 100nF  [C0402]  (hidden comment: Capacitor)
C17  value 100nF  [C0402]  (hidden comment: Capacitor)
C19  value 100nF  [C0402]  (hidden comment: Capacitor)
CN1  value USB_C_12401826E412A  [CON_USB-TYPEC_AMPHENOL_12401826E412A]  (hidden comment: USB_TYPE_C_Receptacle)
CN4  value Header 5x2  [CON_STDC14_Receiver_MEDIUM_WITH_MIPI10_3D]  (hidden comment: Header 7x2)
CN11  Header 4x1  [CON_SAMTEC_TSW-104-07-G-S]
CN12  Jumper_Header 2x1 Fitted  [CON_SAMTEC_TSW-102-07-G-S]  (value not drawn)
D1  BAT60JFILM  [DIO_SOD323]
D2  BAT60JFILM  [DIO_SOD323]
HW6  Shunt Black 2.54mm  (value not drawn)  (mechanical)
HW8  Shunt Black 2.54mm  (value not drawn)  (mechanical)
HW11  Shunt Black 2.54mm  (value not drawn)  (mechanical)
HW12  Shunt Black 2.54mm  (value not drawn)  (mechanical)
HW13  Shunt Black 2.54mm  (value not drawn)  (mechanical)
HW14  Shunt Black 2.54mm  (value not drawn)  (mechanical)
JP2  Jumper_Header 2x1 Fitted  [CON_SAMTEC_TSW-102-07-G-S]  (value not drawn)
JP3  Jumper_Header 2x1  [CON_SAMTEC_TSW-102-07-G-S]  (value not drawn)
JP4  Jumper_Header 2x1 Fitted  [CON_SAMTEC_TSW-102-07-G-S]  (value not drawn)
JP6  Jumper_Header 2x1 Fitted  [CON_SAMTEC_TSW-102-07-G-S]  (value not drawn)
JP7  Jumper_Header 2x1 Fitted  [CON_SAMTEC_TSW-102-07-G-S]  (value not drawn)
JP8  Jumper_Header 2x1 Fitted  [CON_SAMTEC_TSW-102-07-G-S]  (value not drawn)
LD4  value Red/Green  [LED_BI-GR_WE-150141SV73110]  (hidden comment: LED_BICOLOR)
LD5  value Red  [LED_0402_KINGBRIGHT_KPHHS-1005SURCK_HYPER-RED_1A2K_H0P5]  (hidden comment: LED_red)
R1  value 100K  [R0402]  (hidden comment: Resistor)
R2  value 100K  [R0402]  (hidden comment: Resistor)
R3  value 36K  [R0402]  (hidden comment: Resistor)
R4  value 1K5  [R0402]  (hidden comment: Resistor)
R5  value 10K  [R0402]  (hidden comment: Resistor)
R6  value 100R  [R0402]  (hidden comment: Resistor)
R7  value 10K  [R0402]  (hidden comment: Resistor)
R8  value 100K  [R0402]  (hidden comment: Resistor)
R9  value 5K1  [R0402]  (hidden comment: Resistor)
R10  value 1K  [R0402]  (hidden comment: Resistor)
R11  value 330R  [R0402]  (hidden comment: Resistor)
R12  value 1K  [R0402]  (hidden comment: Resistor)
R13  value 10K  [R0402]  (hidden comment: Resistor)
R14  value 100R  [R0402]  (hidden comment: Resistor)
R17  value 5K1  [R0402]  (hidden comment: Resistor)
R18  value 10K  [R0402]  (hidden comment: Resistor)
R19  value 5K1  [R0402]  (hidden comment: Resistor)
R20  value 680K  [R0402]  (hidden comment: Resistor)
R21  value 180K  [R0402]  (hidden comment: Resistor)
R22  value 0R  [R0402]  (hidden comment: Resistor)
R23  value 100R  [R0402]  (hidden comment: Resistor)
R24  value 10K  [R0402]  (hidden comment: Resistor)
R25  value 10K  [R0402]  (hidden comment: Resistor)
R26  value 33R  [R0402]  (hidden comment: Resistor)
R27  value 0R  [R0402]  (hidden comment: Resistor)
T1  value BSR14  [NPN_SOT23]  (hidden comment: 9013-SOT23)
TP1  Test Point  [TP_SMD_1MM]  (value not drawn)  (no BOM)
TP2  Test Point  [TP_SMD_1MM]  (value not drawn)  (no BOM)
U1  STMPS2141STR  [MOS_SOT23-5L]
U2  value ESDA25P35-1U1M  [ESD_QFN1610_2N_1K_2A]  (hidden comment: ESD-TRANSIL)
U3  STLINK-V2EC  [ICC_LQFP48_7X7_P050]  (part A of 2)
U4  ESDALC6V1W5  [ESD_SOT323-5L]
U5  USBLC6-2SC6  [ESD_SOT23-6L]
U6  FPF3380UCX  [ICC_WLCSP12_1P858x1P318_P040]
U7  LDK120M33R  [REG_SOT23-5L]
U8  ESDALC6V1W5  [ESD_SOT323-5L]
X1  value 8MHz  [CRY_NX3225GD_2P]  (hidden comment: XTAL_2_PINS)

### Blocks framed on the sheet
INTERFACE WITH TARGET MCU: R5 R9
USB Re-enumeration pull-up: R3 R4 R6 R7 T1
Jumper for GND between SWDIO and SWCLK: CN12 HW14
VBUS OVP: C7 C11 R20 R21 TP1 U6
LED STLINK: LD4 R11 R12
STDC14 RECEIVER: CN4 R14 R22 U4 U8
ST-LINK POWER (3V3/200mA): C13-C17 D1 D2 U7
5V_STLK power switch (5V/500mA): C1 C4 LD5 R1 R2 R10 U1

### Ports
MCU (harness MCU), NRST

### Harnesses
MCU: MCO, SWDIO, SWO, VCP_TX, SWCLK, VCP_RX

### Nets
3V3: CN4.3 JP8.1(COMMON) U8.4(IO3)
3V3_STLK: C2.1 C3.1 C5.1 C14.2 C16.2 C19.1 CN11.1 LD4.4(Green_anode) T1.3(C) U3.1(VBAT) U3.9(VDDA) U3.24(VDD) U3.36(VDD) U3.48(VDD) U7.5(VOUT)
5V: D2.1(A) R9.2
5V_STLK: C1.2 U1.1(OUT)
GND: C1.1 C2.2 C3.2 C4.1 C5.2 C6.2 C7.2 C8.1 C9.2 C10.1 C11.1 C12.1 C13.1 C14.1 C15.1 C16.1 C17.1 C19.2 CN1.A1(GND1) CN1.A12(GND2) CN1.B1(GND3) CN1.B12(GND4) CN1.SH1(Shield1) CN1.SH2(Shield2) CN1.SH3(Shield3) CN1.SH4(Shield4) CN4.5 CN4.7 CN11.3 CN12.1(COMMON) CN12.2(NO) JP3.2(NO) LD4.3(RED_cathode) R3.1 R5.2 R8.1 R13.2 R14.1 R17.2 R18.2 R19.2 R21.1 R24.2 U1.2(GND) U2.2(GND) U3.8(VSSA) U3.20(PB2/BOOT1) U3.23(VSS) U3.35(VSS) U3.47(VSS) U4.2(GND) U5.2(GND) U6.A1(~{EN}) U6.A4(GND) U6.B4(GND) U6.C4(GND) U7.2(GND) U8.2(GND)
T_VCC: JP8.2(NO) R25.2
VBUS: C6.1 C7.1 CN1.A4(VBUS1) CN1.A9(VBUS2) CN1.B4(VBUS3) CN1.B9(VBUS4) R20.2 U2.1(IO1) U6.B3(IN) U6.C2(IN) U6.C3(IN)
VBUS_STLK: C4.2 C11.2 D1.1(A) R1.2 R2.2 R7.2 R10.2 U1.5(IN) U6.A2(OUT) U6.A3(OUT) U6.B2(OUT)
GNDDetect: CN4.11 R14.2 U4.4(IO3)
MCU.MCO: C10.2 R23.2 TP2.1 ; port MCU.MCO
MCU.SWCLK: CN4.6 JP4.1(COMMON) R22.1 U4.1(IO1) ; port MCU.SWCLK
MCU.SWDIO: CN4.4 JP2.1(COMMON) U4.5(IO4) ; port MCU.SWDIO
MCU.SWO: CN4.8 JP6.1(COMMON) U4.3(IO2) ; port MCU.SWO
MCU.VCP_RX: CN4.13 R26.2 U8.3(IO2) ; port MCU.VCP_RX
MCU.VCP_TX: CN4.14 R27.2 U8.1(IO1) ; port MCU.VCP_TX
NRST: CN4.12 JP7.1(COMMON) U8.5(IO4) ; port NRST
STLK_LED: R11.1 R12.2 U3.30(STLK_LED/PA9)
STLK_NRST: C12.2 JP3.1(COMMON) U3.7(NRST)
STLK_OSC_IN: C8.2 U3.5(OSCIN) X1.2(X2)
STLK_OSC_OUT: C9.1 U3.6(OSCOUT) X1.1(X1)
STLK_SWCLK: CN11.2 U3.37(STLK_SWCLK/PA14)
STLK_SWDIO: CN11.4 U3.34(STLK_SWDIO/PA13)
STLK_USB_N: CN1.A7(D-1) CN1.B7(D-2) U3.32(USP_DM/PA11) U5.3(IO_2) U5.4(IO2)
STLK_USB_P: CN1.A6(D+1) CN1.B6(D+2) R4.1 U3.33(USP_DP/PA12) U5.1(IO_1) U5.6(IO1)
STLK_VCP_RX: R27.1 U3.13(STLK_VCP_RX/PG9/PA3)
STLK_VCP_TX: R26.1 U3.12(STLK_VCP_TX/PA2)
T_NRST: JP7.2(NO) U3.18(T_NRST/PB0)
T_PWR_EN: R1.1 U1.4(~{EN}) U3.28(T_PWR_EN/PB15)
T_PWR_EXT: R5.1 R9.1 U3.39(T_PWR_EXT/PB3)
T_SWCLK: JP4.2(NO) U3.15(T_SWCLK/PA5) U3.22(T_JCLK_OUT/PB11) U3.26(T_JRCLK/PB13)
T_SWDIO: JP2.2(NO) U3.25(T_SWDIO_IN/PB12) U3.27(T_JTMS/T_SWDIO_OUT/PB14)
T_SWO: JP6.2(NO) U3.16(T_JTDO/PA6) U3.31(T_SWO/PA10)
T_VCC_AIN: R24.1 R25.1 U3.10(T_VCC_AIN/PA0)
USB_RENUMn: R6.2 U3.38(USB_RENUMn/PA15)
NetC13_2: C13.2 U7.4(BYPASS)
NetC15_2: C15.2 C17.2 D1.2(K) D2.2(K) U7.1(VIN) U7.3(EN)
NetCN1_A5: CN1.A5(CC1) R19.1
NetCN1_B5: CN1.B5(CC2) R17.1
NetCN4_9: CN4.9 R22.2
NetLD4_1: LD4.1(Red_anode) R12.1
NetLD4_2: LD4.2(Green_cathode) R11.2
NetLD5_1: LD5.1 R10.1
NetLD5_2: LD5.2 R2.1 U1.3(~{FAULT})
NetR3_2: R3.2 R6.1 R7.1 T1.1(B)
NetR4_2: R4.2 T1.2(E)
NetR8_2: R8.2 U3.44(BOOT0)
NetR13_1: R13.1 U3.2(HW_TYP_0/PC13)
NetR18_1: R18.1 U3.3(HW_TYP_0/PC14)
NetR20_1: R20.1 R21.2 U6.C1(OVLO)
NetR23_1: R23.1 U3.29(T_MCO/PA8)
NetTP1_1: TP1.1 U6.B1(~{ACOK})

Not connected (* = marked no-connect by the designer): CN1 A2(TX1+)* A3(TX1-)* A8(SBU1)* A10(RX2-)* A11(RX2+)* B2(TX2+)* B3(TX2-)* B8(SBU2)* B10(RX1-)* B11(RX1+)*; CN4 1* 2* 10*; U5 5(VBUS)*

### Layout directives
differential pair; rule Impedance Constraint [Min = 85.00    Max = 95.00    ]: STLK_USB_N, STLK_USB_P

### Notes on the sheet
- STLINK-V2EC
- (near C10) DNF
- STLINK
- MCO
- JPxx OFF
- DEBUG OUT
- TARGET MCU
- STLK_RST
- Target external supply
- Target Vio reference
- source indicator
- (near R18) Board Ident: PC13=0
- (near R18) DNF
- (near CN11) RESERVED
- (near CN11) DNF
- (near CN4) JTCK
- (near CN4) JTMS
- (near LD4) COM
- (near CN4) KEY
- (near CN4) JRTCK
- (near CN4) JTDO
- Vo=(680+180)/180*1.2=5.73V
- (near CN4) DEBUG_IN

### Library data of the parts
C1-C3 C5 C12 C16 C17 C19 = MCD-00006: as C20 on sheet Power
C4 = MCD-00006: as C36 on sheet STM32_microcontroller_IOs
C6 = MCD-00205: Capacitor, MLCC, 100pF, 50V, NPO, +/-5%, 0402, T=0.5mm; Part_Preference: Recommended; Manufacturer: YAGEO; Manufacturer_Part_Number: CC0402JRNPO9BN101; Component_Country_Of_Origin: China; ShowFields: YES; ID: 2658
C7 = MCD-01099: Capacitor, MLCC, 100nF, 50V, X7R, +/-10%, 0603, T=0.8mm; Manufacturer_Part_Number: CC0603KRX7R9BB104; Manufacturer: YAGEO; BMS_Part_Number: 9142278; Part_Preference: Recommended; Order_Code_RS: 669-8767; Component_Country_Of_Origin: China; ShowFields: YES; ID: 3397
C8 C9 = MCD-00015: Capacitor, MLCC, 10pF, 50V, NPO, +/-5%, 0402, T=0.5mm; Manufacturer_Part_Number: CC0402JRNPO9BN100; Manufacturer: YAGEO; Part_Preference: Recommended; Order_Code_RS: 3019160RL; Component_Country_Of_Origin: China; ShowFields: YES; ID: 2465
C10 = MCD-00016: Capacitor, MLCC, 20pF, 50V, NPO, +/- 5%, 0402, T=0.5mm; Manufacturer_Part_Number: CC0402JRNPO9BN200; Manufacturer: YAGEO; Part_Preference: Recommended; Component_Country_Of_Origin: China; ShowFields: YES; ID: 2479
C11 = MCD-00099: Capacitor, MLCC, 10uF, 10V, X5R, +/-10%, 0603, T=0.8mm; Part_Preference: Recommended; Manufacturer: MURATA; Manufacturer_Part_Number: GRM188R61A106KE69D; Partial_Alternate_Internal_Part_Number: MCD-03152; Order_Code_RS: 2494233; Component_Country_Of_Origin: Japan°°; ShowFields: YES; ID: 2770
C13 = MCD-02198: Capacitor, MLCC, 10nF, 50V, X7R, +/-10%, 0402, T=0.5mm; Manufacturer_Part_Number: CC0402KRX7R9BB103; Manufacturer: YAGEO; Part_Preference: Recommended; Order_Code_RS: 6169644; Component_Country_Of_Origin: China; ShowFields: YES; ID: 4298
C14 C15 = MCD-00010: as C18 on sheet Power
CN1 = MCD-03232: USB_TypeC, 24 pins, RA, SMD, T=2.96mm; Part_Type: Connector; Part_Preference: Recommended; Manufacturer: AMPHENOL CS; Manufacturer_Part_Number: 12401826E412A; Component_Country_Of_Origin: China°; ShowFields: YES; ID: 5348
CN4 = MCD-01226: Header, 5x2, 1.27mm, VR, SMD, T=7.02mm; Part_Type: Connector; Manufacturer_Part_Number: FTSH-105-01-L-DV-K; Manufacturer: SAMTEC; Part_Preference: Recommended; Partial_Alternate_Internal_Part_Number: MCD-02956, MCD-03788; Order_Code_RS: 159-2332; Component_Country_Of_Origin: China, Costa Rica, Malaysia, USA, Vietnam; ShowFields: YES; ID: 3265
CN11 = MCD-00029: Header, 4x1, 2.54mm, VR, TH, T=5.84mm/2.54mm; Manufacturer_Part_Number: TSW-104-07-G-S; Manufacturer: SAMTEC; Part_Type: Connector; Part_Preference: Recommended; Order_Code_RS: 161-2460; Component_Country_Of_Origin: China, Costa Rica, Malaysia, USA, Vietnam; ShowFields: YES; ID: 2487
CN12 JP2 JP4 JP6-JP8 = MCD-00683: as JP5 on sheet Power
D1 D2 = MCD-00034: Diode, Schottky, 0V53, 1A, 10V, SOD323; Manufacturer: STMICROELECTRONICS; BMS_Part_Number: 9151097; Part_Preference: Recommended; Manufacturer_HQ_COO: EU; Component_Country_Of_Origin: China; ShowFields: YES; ID: 2483; Order_Code_RS: 714-6879
HW6 HW8 HW11-HW14 = MCD-00043: as HW3 on sheet Power
JP3 = MCD-00045: Header, 2x1, 2.54mm, VR, TH, T=5.84mm/2.54mm; Part_Preference: Recommended; Part_Type: Connector; Manufacturer: SAMTEC; Manufacturer_Part_Number: TSW-102-07-G-S; Full_Alternate_Internal_Part_Number: MCD-02390; Partial_Alternate_Internal_Part_Number: MCD-02957, MCD-03720, MCD-04249; Order_Code_RS: 2505044; Component_Country_Of_Origin: China, Costa Rica, Malaysia, USA, Vietnam; ShowFields: YES; ID: 2545
LD4 = MCD-02631: LED Bicolor, Red/Green, 2V, 20mA, 4-PLCC; Part_Type: Display; Part_Preference: Recommended; Manufacturer: WURTH ELEKTRONIK; Manufacturer_Part_Number: 150141SV73110; Partial_Alternate_Internal_Part_Number: MCD-02402; Order_Code_RS: 184-6963; Component_Country_Of_Origin: China; ShowFields: YES; ID: 4737
LD5 = MCD-00708: LED, Red, 1V95, 20mA, 0402; Part_Type: Display; Manufacturer_Part_Number: KPHHS-1005SURCK; Manufacturer: KINGBRIGHT; Part_Preference: Recommended; Component_Country_Of_Origin: Unknown; ShowFields: YES; ID: 3037; Order_Code_RS: 466-3633
R1 R2 R8 = MCD-00059: Resistor, 100K, 0402, +/-1%, 1/16W; Manufacturer_Part_Number: RC0402FR-07100KL; Manufacturer: YAGEO; Part_Preference: Recommended; Partial_Alternate_Internal_Part_Number: MCD-03301; Order_Code_RS: 2421891; Component_Country_Of_Origin: China; ShowFields: YES; ID: 2533
R3 = MCD-00069: Resistor, 36K, 0402, +/-1%, 1/16W; Manufacturer_Part_Number: RC0402FR-0736KL; Manufacturer: YAGEO; Part_Preference: Recommended; Order_Code_RS: 1458788; Component_Country_Of_Origin: China; ShowFields: YES; ID: 2523
R4 = MCD-00068: Resistor, 1K5, 0402, +/-1%, 1/16W; Manufacturer_Part_Number: RC0402FR-071K5L; Manufacturer: YAGEO; Part_Preference: Recommended; Order_Code_RS: 9239251; Component_Country_Of_Origin: China; ShowFields: YES; ID: 2524
R5 R13 R18 R24 R25 = MCD-00053: Resistor, 10K, 0402, +/-1%, 1/16W; Manufacturer_Part_Number: RC0402FR-0710KL; Manufacturer: YAGEO; BMS_Part_Number: 9131590; Part_Preference: Recommended; Order_Code_RS: 9239359; Component_Country_Of_Origin: China; ShowFields: YES; ID: 2539
R6 = MCD-00067: as R41 on sheet STM32_microcontroller_IOs
R7 = MCD-00053: Resistor, 10K, 0402, +/-1%, 1/16W; Manufacturer_Part_Number: RC0402FR-0710KL; Manufacturer: YAGEO; Part_Preference: Recommended; BMS_Part_Number: 9131590; Order_Code_RS: 9239359; Component_Country_Of_Origin: China; ShowFields: YES; ID: 2539
R9 R17 R19 = MCD-00333: Resistor, 5K1, 0402, +/-1%, 1/16W; Part_Preference: Recommended; Manufacturer: YAGEO; Manufacturer_Part_Number: RC0402FR-075K1L; Component_Country_Of_Origin: China; ShowFields: YES; ID: 2944
R10 = MCD-00061: Resistor, 1K, 0402, +/-1%,1/16W; Manufacturer_Part_Number: RC0402FR-071KL; Manufacturer: YAGEO; Part_Preference: Recommended; Order_Code_RS: 9239235; Component_Country_Of_Origin: China; ShowFields: YES; ID: 2532
R11 = MCD-00062: Resistor, 330R, 0402, +/-1%, 1/16W; Part_Preference: Recommended; Manufacturer: YAGEO; Manufacturer_Part_Number: RC0402FR-07330RL; Order_Code_RS: 9239170; Component_Country_Of_Origin: China; ShowFields: YES; ID: 2529
R12 = MCD-00061: Resistor, 1K, 0402, +/-1%,1/16W; Part_Preference: Recommended; Manufacturer: YAGEO; Manufacturer_Part_Number: RC0402FR-071KL; Order_Code_RS: 9239235; ShowFields: YES; ID: 2532; Component_Country_Of_Origin: China
R14 R23 = MCD-00067: Resistor, 100R, 0402, +/- 1%, 1/16W; Part_Preference: Recommended; Manufacturer: YAGEO; Manufacturer_Part_Number: RC0402FR-07100RL; Order_Code_RS: 9239111; Component_Country_Of_Origin: China; ShowFields: YES; ID: 2527
R20 = MCD-00513: Resistor, 680K, 0402, +/-1%, 1/16W; Manufacturer_Part_Number: RC0402FR-07680KL; Manufacturer: YAGEO; Part_Preference: Recommended; Component_Country_Of_Origin: China; ShowFields: YES; ID: 3227
R21 = MCD-00413: Resistor, 180K, 0402, +/-1%, 1/16W; Manufacturer_Part_Number: RC0402FR-07180KL; Manufacturer: YAGEO; Part_Preference: Recommended; Component_Country_Of_Origin: China; ShowFields: YES; ID: 2864
R22 R27 = MCD-00052: Resistor, 0R, 0402, +/-5%, 1/16W; Part_Preference: Recommended; Manufacturer: YAGEO; Manufacturer_Part_Number: RC0402JR-070RL; Order_Code_RS: 9232516RL; Component_Country_Of_Origin: China; ShowFields: YES; ID: 2540
R26 = MCD-00455: Resistor, 33R, 0402, +/-1%, 1/16W; Part_Preference: Recommended; Manufacturer: YAGEO; Manufacturer_Part_Number: RC0402FR-0733RL; Component_Country_Of_Origin: China; ShowFields: YES; ID: 2821
T1 = MCD-00073: Transistor, NPN, 40V, 800mA, SOT23; Manufacturer: ON SEMICONDUCTOR; Part_Preference: Recommended; Partial_Alternate_Internal_Part_Number: MCD-01737, MCD-03305, , MCD-02988; Component_Country_Of_Origin: Unknown; ShowFields: YES; ID: 2519
TP1 TP2 = MCD-00074: as TP3 on sheet Power
U1 = MCD-00083: Power Switch, Enhanced single channel; Part_Type: IC; Manufacturer: STMICROELECTRONICS; BMS_Part_Number: 9159003; Part_Preference: Recommended; Manufacturer_HQ_COO: EU; Component_Country_Of_Origin: Malaysia; ShowFields: YES; ID: 2509; Order_Code_RS: 880-5406
U2 = MCD-01207: Diode, ESD TVS, 22V, 200nA, 25V8, QFN1610; Manufacturer: STMICROELECTRONICS; BMS_Part_Number: 9179045; Part_Preference: Recommended; Manufacturer_HQ_COO: EU; Component_Country_Of_Origin: China; ShowFields: YES; ID: 3289; Order_Code_RS: 163-9774
U3 = MCD-03850: MCU, ARM Cortex-M3 32-bit, 128KB Flash, 20KB RAM, No Crypto; Part_Type: IC; Part_Preference: Recommended; Manufacturer: STMICROELECTRONICS; Manufacturer_Part_Number: STM32F103CBT6; Order_Code_RS: 402-273P; ShowFields: YES; ID: 5966; Component_Country_Of_Origin: Malaysia
U4 U8 = MCD-00136: Diode, ESD Transil, 3V, 1uA, 7V2, SOT323-5; BMS_Part_Number: 9151112; Part_Preference: Recommended; Manufacturer: STMICROELECTRONICS; Manufacturer_HQ_COO: EU; Component_Country_Of_Origin: China; Order_Code_RS: 178-7373; ShowFields: YES; ID: 2731
U5 = MCD-00163: Diode, ESD protection, 5V25, 150nA, 6V, SOT23-6; Manufacturer: STMICROELECTRONICS; BMS_Part_Number: 9151075; Part_Preference: Recommended; Order_Code_RS: 920-6266; Component_Country_Of_Origin: China; ShowFields: YES; ID: 2707
U6 = MCD-03166: Power switch, 28V/5A OVP with Low On-resistance, Integrated TVS; Part_Type: IC; Part_Preference: Recommended; Manufacturer: ON SEMICONDUCTOR; Partial_Alternate_Internal_Part_Number: MCD-03058; ShowFields: YES; ID: 5282; Component_Country_Of_Origin: Philippines
U7 = MCD-00663: LDO, 3V3, 200mA, Low quiescent current, Very low noise; Part_Type: IC; Manufacturer: STMICROELECTRONICS; BMS_Part_Number: 9176330; Part_Preference: Recommended; Manufacturer_HQ_COO: EU; Partial_Alternate_Internal_Part_Number: MCD-03279; Component_Country_Of_Origin: China; ShowFields: YES; ID: 3082; Order_Code_RS: 188-9202
X1 = MCD-00092: Crystal, 8MHz, 8pF, +/-20ppm, 500R, 3.2x2.5mm; Part_Type: Crystal_Osc; Manufacturer_Part_Number: NX3225GD-8MHZ-EXS00A-CG04874; Manufacturer: NDK; BMS_Part_Number: 9157029; Part_Preference: Recommended; Component_Country_Of_Origin: Unknown; ShowFields: YES; ID: 2776

## Sheet USB-C_Device.SchDoc: USB-C_Device
size A4; Date: Not used; ApprovedBy: Not used; CheckedBy: Not used; Author: Not used; CompanyName: STMicroelectronics; DrawnBy: Not used; Engineer: Not used; Organization: Not used; Address1: Not used; Address2: Not used; Address3: Not used; Address4: Not used; DocumentNumber: Not used; Revision: V0.1; SheetNumber: 5; SheetTotal: 8
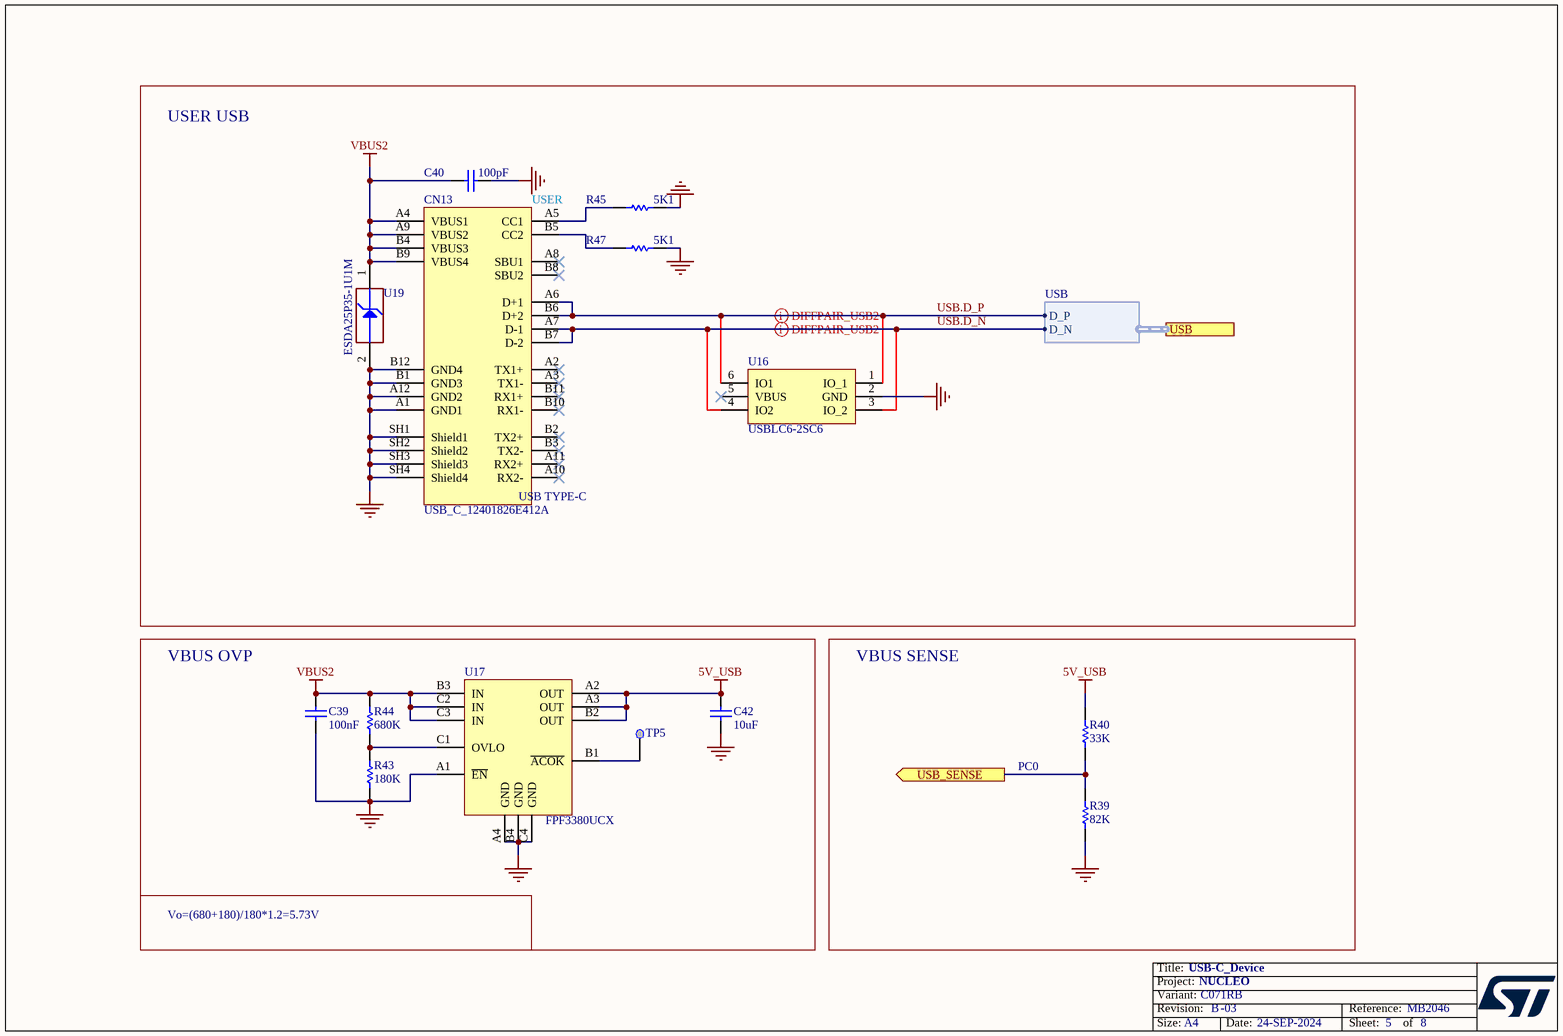
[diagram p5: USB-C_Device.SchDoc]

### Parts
C39  value 100nF  [C0603]  (hidden comment: Capacitor)
C40  value 100pF  [C0402]  (hidden comment: Capacitor)
C42  value 10uF  [C0603]  (hidden comment: Capacitor)
CN13  value USB_C_12401826E412A  [CON_USB-TYPEC_AMPHENOL_12401826E412A]  (hidden comment: USB_TYPE_C_Receptacle)
R39  value 82K  [R0402]  (hidden comment: Resistor)
R40  value 33K  [R0402]  (hidden comment: Resistor)
R43  value 180K  [R0402]  (hidden comment: Resistor)
R44  value 680K  [R0402]  (hidden comment: Resistor)
R45  value 5K1  [R0402]  (hidden comment: Resistor)
R47  value 5K1  [R0402]  (hidden comment: Resistor)
TP5  Test Point  [TP_SMD_1MM]  (value not drawn)  (no BOM)
U16  USBLC6-2SC6  [ESD_SOT23-6L]
U17  value FPF3380UCX  [ICC_WLCSP12_1P858x1P318_P040]  (hidden comment: AW329xxFCR)
U19  value ESDA25P35-1U1M  [ESD_QFN1610_2N_1K_2A]  (hidden comment: ESD-TRANSIL)

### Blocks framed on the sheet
USER USB: C40 CN13 R45 R47 U16 U19
VBUS OVP: C39 C42 R43 R44 TP5 U17
VBUS SENSE: R39 R40

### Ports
USB (harness USB), USB_SENSE (out)

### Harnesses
USB: D_P, D_N

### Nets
5V_USB: C42.2 R40.2 U17.A2(OUT) U17.A3(OUT) U17.B2(OUT)
GND: C39.2 C40.2 C42.1 CN13.A1(GND1) CN13.A12(GND2) CN13.B1(GND3) CN13.B12(GND4) CN13.SH1(Shield1) CN13.SH2(Shield2) CN13.SH3(Shield3) CN13.SH4(Shield4) R39.1 R43.1 R45.2 R47.2 U16.2(GND) U17.A1(~{EN}) U17.A4(GND) U17.B4(GND) U17.C4(GND) U19.2(GND)
VBUS2: C39.1 C40.1 CN13.A4(VBUS1) CN13.A9(VBUS2) CN13.B4(VBUS3) CN13.B9(VBUS4) R44.2 U17.B3(IN) U17.C2(IN) U17.C3(IN) U19.1(IO1)
PC0: R39.2 R40.1 ; port USB_SENSE
USB.D_N: CN13.A7(D-1) CN13.B7(D-2) U16.3(IO_2) U16.4(IO2) ; port USB.D_N
USB.D_P: CN13.A6(D+1) CN13.B6(D+2) U16.1(IO_1) U16.6(IO1) ; port USB.D_P
NetCN13_A5: CN13.A5(CC1) R45.1
NetCN13_B5: CN13.B5(CC2) R47.1
NetR43_2: R43.2 R44.1 U17.C1(OVLO)
NetTP5_1: TP5.1 U17.B1(~{ACOK})

Not connected (* = marked no-connect by the designer): CN13 A2(TX1+)* A3(TX1-)* A8(SBU1)* A10(RX2-)* A11(RX2+)* B2(TX2+)* B3(TX2-)* B8(SBU2)* B10(RX1-)* B11(RX1+)*; U16 5(VBUS)*

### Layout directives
differential pair; rule Impedance Constraint [Min = 85.00    Max = 95.00    ]: USB.D_N, USB.D_P

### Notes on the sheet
- (near CN13) USER
- PC0
- Vo=(680+180)/180*1.2=5.73V

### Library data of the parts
C39 = MCD-01099: as C7 on sheet STLINK_V2EC
C40 = MCD-00205: as C6 on sheet STLINK_V2EC
C42 = MCD-00099: as C11 on sheet STLINK_V2EC
CN13 = MCD-03232: as CN1 on sheet STLINK_V2EC
R39 = MCD-00531: Resistor, 82K, 0402, +/-1%, 1/16W; Part_Preference: Recommended; Manufacturer: YAGEO; Manufacturer_Part_Number: RC0402FR-0782KL; Component_Country_Of_Origin: China; ShowFields: YES; ID: 3207
R40 = MCD-00258: Resistor, 33K, 0402, +/-1%, 1/16W; Part_Preference: Recommended; Manufacturer: YAGEO; Manufacturer_Part_Number: RC0402FR-0733KL; Component_Country_Of_Origin: China; ShowFields: YES; ID: 2611
R43 = MCD-00413: as R21 on sheet STLINK_V2EC
R44 = MCD-00513: as R20 on sheet STLINK_V2EC
R45 R47 = MCD-00333: as R9 on sheet STLINK_V2EC
TP5 = MCD-00074: as TP3 on sheet Power
U16 = MCD-00163: as U5 on sheet STLINK_V2EC
U17 = MCD-03166: as U6 on sheet STLINK_V2EC
U19 = MCD-01207: as U2 on sheet STLINK_V2EC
